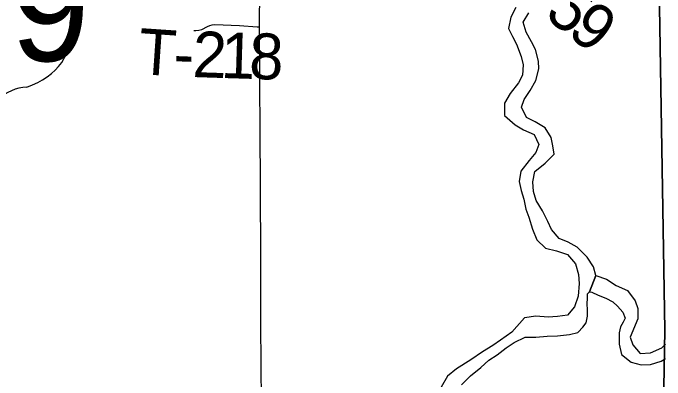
# Model space of a CAD drawing. Extents: x 0 to 45.9, y 0 to 22.
# Drawn here: x 4.674 to 5.48, y 18.26 to 18.714 of the extents above; entities that cross this region are included whole.
import ezdxf

# ---------------------------------------------------------------- set-up
doc = ezdxf.new("R2010")
doc.units = 0
for name, color, linetype in [('Default', 7, 'Continuous'), ('GM_X_Major_River', 7, 'Continuous'), ('GM_X_Minor_River', 7, 'Continuous'), ('GM_X_State_Route', 7, 'Continuous'), ('GM_X_State_Shield', 7, 'Continuous'), ('GM_X_Township_Road', 7, 'Continuous'), ('GM_X_Township_Road_Text', 7, 'Continuous'), ('SH_Text', 7, 'Continuous')]:
    doc.layers.add(name, color=color, linetype=linetype)

msp = doc.modelspace()

# ---------------------------------------------------------------- linework, layer by layer
at = {"layer": 'Default'}
msp.add_lwpolyline([(2.1, 19.71136), (2.1, 14.1), (5.4538, 14.1), (5.46055, 15.65881), (5.46505, 16.7018), (5.46936, 17.70607), (5.48021, 18.3214), (5.47374, 18.72155), (5.47524, 19.0482), (5.47587, 19.21088), (5.47734, 19.71076), (5.08255, 19.71199), (3.73665, 19.70719), (2.14996, 19.71128)], close=True, dxfattribs=at)
msp.add_lwpolyline([(5.47734, 19.71076), (5.47587, 19.21088), (5.47524, 19.0482), (5.47374, 18.72155), (5.48021, 18.3214), (5.46936, 17.70607), (5.46505, 16.7018), (5.46055, 15.65881), (5.4538, 14.1)], dxfattribs=at)
at = {"layer": 'GM_X_Major_River'}
for points in [[(5.29576, 18.72084), (5.28944, 18.70882), (5.2865, 18.69482), (5.29159, 18.68484), (5.29669, 18.67524), (5.30243, 18.66031), (5.30486, 18.65), (5.30421, 18.6371), (5.29908, 18.62734), (5.28896, 18.61426), (5.28189, 18.60225), (5.28195, 18.58706), (5.29496, 18.57539), (5.30544, 18.56948), (5.31856, 18.56351), (5.32436, 18.55123), (5.32037, 18.54144), (5.3122, 18.53136), (5.30208, 18.51828), (5.29992, 18.50541), (5.30234, 18.49434), (5.30552, 18.48364), (5.30828, 18.47105), (5.31186, 18.4611), (5.31647, 18.44657), (5.32187, 18.43317), (5.33263, 18.42269), (5.3462, 18.41975), (5.35973, 18.41491), (5.36971, 18.40331), (5.37322, 18.39032), (5.37412, 18.37929), (5.37303, 18.36336), (5.36858, 18.35016), (5.35965, 18.33971), (5.3475, 18.33807), (5.33576, 18.33755), (5.32063, 18.33863), (5.30658, 18.33664), (5.29071, 18.31903)], [(5.39479, 18.38888), (5.39197, 18.39981), (5.38389, 18.41175), (5.37166, 18.42416), (5.36043, 18.43047), (5.34955, 18.43487), (5.33994, 18.44609), (5.33522, 18.45568), (5.32869, 18.46911), (5.321, 18.4818), (5.31745, 18.49289), (5.31695, 18.50505), (5.31912, 18.51792), (5.33221, 18.52828), (5.34304, 18.53907), (5.34137, 18.54974), (5.3393, 18.55966), (5.33199, 18.57196), (5.31965, 18.57943), (5.30878, 18.5846), (5.30299, 18.59725), (5.30623, 18.60706), (5.31365, 18.61792), (5.32073, 18.63031), (5.32406, 18.64467), (5.32389, 18.65455), (5.32002, 18.66868), (5.3153, 18.67827), (5.30836, 18.69019), (5.30484, 18.7028), (5.31189, 18.71404)], [(5.38689, 18.36882), (5.39479, 18.38888)], [(5.37293, 18.31874), (5.37882, 18.32506), (5.38268, 18.33032), (5.38432, 18.33864), (5.38442, 18.34623), (5.38415, 18.3542), (5.38461, 18.36064), (5.38431, 18.36633), (5.38689, 18.36882)], [(5.29071, 18.31903), (5.27691, 18.30898), (5.26733, 18.30228), (5.2547, 18.29448), (5.24015, 18.28443), (5.22216, 18.2733), (5.21104, 18.26434), (5.20326, 18.25079)], [(5.30725, 18.31256), (5.32059, 18.31256), (5.33465, 18.31389), (5.34718, 18.31448), (5.36238, 18.31617), (5.37265, 18.31831), (5.37293, 18.31874)], [(5.22834, 18.25348), (5.23988, 18.26471), (5.25255, 18.27516), (5.26253, 18.28413), (5.27249, 18.29083), (5.28361, 18.2994), (5.29357, 18.3061), (5.30725, 18.31256)]]:
    msp.add_lwpolyline(points, dxfattribs=at)
at = {"layer": 'GM_X_Minor_River'}
for points in [[(5.39479, 18.38888), (5.38689, 18.36882)], [(5.39479, 18.38888), (5.40792, 18.38428), (5.41988, 18.37682), (5.43376, 18.37045), (5.44333, 18.35772), (5.44692, 18.34815), (5.44665, 18.33524), (5.43708, 18.31251)], [(5.38689, 18.36882), (5.39003, 18.36853), (5.39757, 18.36464), (5.40701, 18.3611), (5.41567, 18.35643), (5.42167, 18.35104), (5.42802, 18.34374), (5.43095, 18.33612), (5.42861, 18.33121), (5.4255, 18.32557), (5.4235, 18.31801)], [(5.4235, 18.31801), (5.42369, 18.30397), (5.42655, 18.29141), (5.43856, 18.28176), (5.45104, 18.27856), (5.46243, 18.27878), (5.47576, 18.28278), (5.48102, 18.28631)], [(5.43708, 18.31251), (5.44037, 18.30298), (5.44971, 18.29261), (5.46224, 18.2932), (5.47637, 18.29946), (5.48107, 18.30389)]]:
    msp.add_lwpolyline(points, dxfattribs=at)
at = {"layer": 'GM_X_State_Route'}
msp.add_lwpolyline([(4.98087, 18.22663), (4.98078, 18.28363), (4.98037, 18.32408), (4.9801, 18.433), (4.98001, 18.47656), (4.97962, 18.50457), (4.97926, 18.56368), (4.97909, 18.63215), (4.97873, 18.69684), (4.97865, 18.70995), (4.97881, 18.73064)], dxfattribs=at)
at = {"layer": 'GM_X_State_Shield'}
for centre, major_axis, start_param, end_param in [((4.76854, 18.70037), (0.0248, 0), 2.387724, 3.262537), ((4.65757, 18.68705), (0.08742, 0), 5.101752, 6.440018), ((4.69443, 18.58416), (0.04788, 0), 1.647645, 2.488434)]:
    msp.add_ellipse(centre, major_axis=major_axis, ratio=0.8, start_param=start_param, end_param=end_param, dxfattribs=at)
at = {"layer": 'GM_X_Township_Road'}
msp.add_lwpolyline([(4.89712, 18.69219), (4.89987, 18.69215), (4.90361, 18.69257), (4.9072, 18.69358), (4.91425, 18.69732), (4.91726, 18.69861), (4.91999, 18.69948), (4.92311, 18.69984), (4.95365, 18.6984), (4.97548, 18.69705), (4.97873, 18.69684)], dxfattribs=at)
at = {"layer": 'SH_Text'}
for points in [[(5.4538, 14.1), (5.46055, 15.65881), (5.46505, 16.7018), (5.46936, 17.70607), (5.48021, 18.3214), (5.47374, 18.72155), (5.47524, 19.0482), (5.47587, 19.21088), (5.47734, 19.71076)], [(5.47734, 19.71076), (5.47587, 19.21088), (5.47524, 19.0482), (5.47374, 18.72155), (5.48021, 18.3214), (5.46936, 17.70607), (5.46505, 16.7018), (5.46055, 15.65881), (5.4538, 14.1)]]:
    msp.add_lwpolyline(points, dxfattribs=at)

# ---------------------------------------------------------------- texts
at = {"layer": 'GM_X_State_Shield'}
msp.add_text('309', height=0.131836, dxfattribs=at).set_placement((4.47428, 18.65446))
at = {"layer": 'GM_X_Township_Road_Text'}
for s, rotation, p in [('5', 321.15884, (5.32964, 18.71042)), ('9', 322.08629, (5.35769, 18.68785)), ('T', 356.1101, (4.8272, 18.63863)), ('2', 358.11334, (4.89508, 18.63475)), ('1', 358.21861, (4.93018, 18.6336)), ('8', 358.25658, (4.9652, 18.63251)), ('-', 357.83519, (4.87147, 18.63565))]:
    msp.add_text(s, height=0.05682, rotation=rotation, dxfattribs=at).set_placement(p)

doc.saveas('drawing.dxf')
